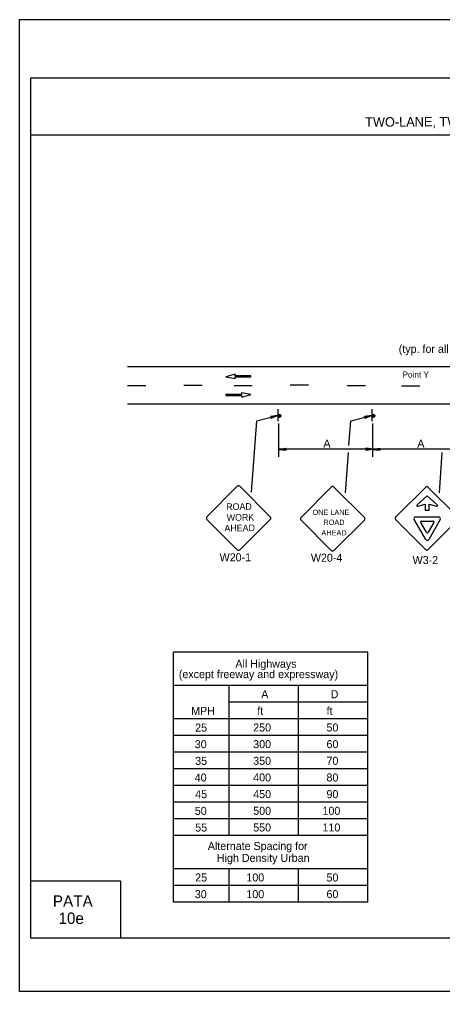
# Model space of a CAD drawing. Extents: x -14145 to -13662, y 30244 to 30661.
# Drawn here: x -13790.17 to -13779.07, y 30505.81 to 30531.31 of the extents above; entities that cross this region are included whole.
import ezdxf

# ---------------------------------------------------------------- set-up
doc = ezdxf.new("R2010")
doc.units = 0
for name, color, linetype in [('1', 7, 'Continuous'), ('10', 7, 'Continuous'), ('2', 7, 'Continuous'), ('3', 7, 'Continuous'), ('4', 7, 'Continuous'), ('61', 7, 'Continuous')]:
    doc.layers.add(name, color=color, linetype=linetype)

msp = doc.modelspace()

# ---------------------------------------------------------------- linework, layer by layer
at = {"layer": '1'}
for p, q in [((-13787.336, 30522.204), (-13761.056, 30522.204)), ((-13784.513, 30522.002), (-13784.754, 30521.935)), ((-13784.513, 30521.956), (-13784.513, 30522.002)), ((-13784.754, 30521.935), (-13784.51, 30521.889)), ((-13784.096, 30521.956), (-13784.513, 30521.956)), ((-13784.51, 30521.889), (-13784.51, 30521.934)), ((-13784.51, 30521.934), (-13784.096, 30521.934)), ((-13784.096, 30521.934), (-13784.096, 30521.956)), ((-13786.856, 30521.694), (-13787.336, 30521.694)), ((-13785.38, 30521.706), (-13785.86, 30521.706)), ((-13784.34, 30521.466), (-13784.754, 30521.466)), ((-13784.754, 30521.466), (-13784.754, 30521.444)), ((-13784.06, 30521.7), (-13784.54, 30521.7)), ((-13784.096, 30521.465), (-13784.34, 30521.511)), ((-13784.34, 30521.511), (-13784.34, 30521.466)), ((-13784.338, 30521.399), (-13784.096, 30521.465)), ((-13782.584, 30521.712), (-13783.064, 30521.712)), ((-13781.09, 30521.7), (-13781.57, 30521.7)), ((-13779.662, 30521.688), (-13780.142, 30521.688)), ((-13787.336, 30521.22), (-13761.056, 30521.22)), ((-13784.754, 30521.444), (-13784.338, 30521.444)), ((-13784.338, 30521.444), (-13784.338, 30521.399)), ((-13783.391, 30521.081), (-13783.391, 30520.769)), ((-13783.391, 30521.081), (-13783.391, 30520.769)), ((-13780.925, 30521.081), (-13780.925, 30520.769)), ((-13780.925, 30521.081), (-13780.925, 30520.769)), ((-13784.081, 30518.904), (-13783.944, 30520.774)), ((-13783.944, 30520.774), (-13783.397, 30520.914)), ((-13783.361, 30519.832), (-13783.361, 30520.706)), ((-13781.525, 30520.131), (-13781.478, 30520.774)), ((-13781.478, 30520.774), (-13780.931, 30520.914)), ((-13780.895, 30519.832), (-13780.895, 30520.706)), ((-13780.895, 30520.036), (-13783.361, 30520.036)), ((-13781.616, 30518.891), (-13781.539, 30519.945)), ((-13778.429, 30520.036), (-13780.895, 30520.036)), ((-13779.15, 30518.891), (-13779.073, 30519.945)), ((-13784.457, 30519.062), (-13785.252, 30518.259)), ((-13783.588, 30518.259), (-13784.391, 30519.062)), ((-13781.987, 30519.041), (-13782.782, 30518.238)), ((-13781.118, 30518.238), (-13781.921, 30519.041)), ((-13780.303, 30518.247), (-13779.507, 30519.041)), ((-13779.455, 30519.041), (-13778.659, 30518.247)), ((-13779.47, 30518.81), (-13779.734, 30518.571)), ((-13779.205, 30518.571), (-13779.47, 30518.81)), ((-13779.718, 30518.54), (-13779.526, 30518.59)), ((-13779.526, 30518.59), (-13779.526, 30518.431)), ((-13779.526, 30518.431), (-13779.414, 30518.431)), ((-13779.414, 30518.431), (-13779.414, 30518.59)), ((-13779.414, 30518.59), (-13779.222, 30518.54)), ((-13785.252, 30518.193), (-13784.457, 30517.398)), ((-13784.391, 30517.398), (-13783.588, 30518.193)), ((-13782.782, 30518.172), (-13781.987, 30517.377)), ((-13781.921, 30517.377), (-13781.118, 30518.172)), ((-13779.507, 30517.398), (-13780.303, 30518.193)), ((-13779.509, 30517.666), (-13779.811, 30518.189)), ((-13779.771, 30518.259), (-13779.167, 30518.259)), ((-13779.618, 30518.15), (-13779.319, 30518.15)), ((-13778.659, 30518.193), (-13779.455, 30517.398)), ((-13779.127, 30518.189), (-13779.428, 30517.666)), ((-13779.491, 30517.853), (-13779.64, 30518.111)), ((-13779.297, 30518.111), (-13779.446, 30517.853)), ((-13786.126, 30508.154), (-13786.126, 30514.71)), ((-13781.027, 30514.71), (-13786.126, 30514.71)), ((-13781.027, 30508.154), (-13781.027, 30514.71)), ((-13781.027, 30513.836), (-13786.128, 30513.836)), ((-13784.669, 30509.902), (-13784.669, 30513.836)), ((-13782.849, 30509.902), (-13782.849, 30513.836)), ((-13781.027, 30513.398), (-13784.669, 30513.398)), ((-13781.027, 30512.961), (-13786.128, 30512.961)), ((-13781.027, 30512.524), (-13786.128, 30512.524)), ((-13781.027, 30512.087), (-13786.128, 30512.087)), ((-13781.027, 30511.65), (-13786.128, 30511.65)), ((-13781.027, 30511.213), (-13786.128, 30511.213)), ((-13781.027, 30510.776), (-13786.128, 30510.776)), ((-13781.027, 30510.339), (-13786.128, 30510.339)), ((-13781.027, 30509.902), (-13786.128, 30509.902)), ((-13781.027, 30509.028), (-13786.128, 30509.028)), ((-13784.669, 30508.154), (-13784.669, 30509.028)), ((-13782.849, 30508.154), (-13782.849, 30509.028)), ((-13781.027, 30508.591), (-13786.128, 30508.591)), ((-13781.027, 30508.154), (-13786.126, 30508.154))]:
    msp.add_line(p, q, dxfattribs=at)
for points in [[(-13783.577, 30520.89), (-13783.565, 30520.878), (-13783.397, 30520.914), (-13783.577, 30520.89), (-13783.583, 30520.896), (-13783.397, 30520.914), (-13783.559, 30520.86), (-13783.565, 30520.848), (-13783.397, 30520.914), (-13783.571, 30520.836), (-13783.565, 30520.848)], [(-13781.111, 30520.89), (-13781.099, 30520.878), (-13780.931, 30520.914), (-13781.111, 30520.89), (-13781.117, 30520.896), (-13780.931, 30520.914), (-13781.093, 30520.86), (-13781.099, 30520.848), (-13780.931, 30520.914), (-13781.105, 30520.836), (-13781.099, 30520.848)], [(-13783.181, 30520.006), (-13783.187, 30520.018), (-13783.361, 30520.03), (-13783.181, 30520.006), (-13783.175, 30520), (-13783.361, 30520.03), (-13783.187, 30520.036), (-13783.181, 30520.048), (-13783.361, 30520.03), (-13783.175, 30520.06), (-13783.181, 30520.048)], [(-13781.075, 30520.06), (-13781.069, 30520.042), (-13780.895, 30520.036), (-13781.075, 30520.06), (-13781.081, 30520.066), (-13780.895, 30520.036), (-13781.069, 30520.03), (-13781.075, 30520.012), (-13780.895, 30520.036), (-13781.081, 30520.006), (-13781.075, 30520.012)], [(-13780.715, 30520.006), (-13780.721, 30520.018), (-13780.895, 30520.03), (-13780.715, 30520.006), (-13780.709, 30520), (-13780.895, 30520.03), (-13780.721, 30520.036), (-13780.715, 30520.048), (-13780.895, 30520.03), (-13780.709, 30520.06), (-13780.715, 30520.048)]]:
    msp.add_lwpolyline(points, dxfattribs=at)
for centre in [(-13783.352, 30520.908), (-13780.886, 30520.908)]:
    msp.add_circle(centre, 0.0408, dxfattribs=at)
for centre, radius, start, end in [((-13783.357, 30520.916), 0.0214, 189.521, 184.2501), ((-13780.891, 30520.916), 0.0214, 189.521, 184.2501), ((-13784.424, 30519.029), 0.0465, 45, 135), ((-13781.954, 30519.008), 0.0465, 45, 135), ((-13779.482, 30519.015), 0.0376, 45, 135), ((-13779.722, 30518.558), 0.0178, 132.5836, 284.3022), ((-13779.217, 30518.558), 0.0178, 255.6978, 47.4164), ((-13785.219, 30518.226), 0.0465, 135, 225), ((-13783.621, 30518.226), 0.0465, 315, 45), ((-13782.749, 30518.206), 0.0465, 135, 225), ((-13781.151, 30518.205), 0.0465, 315, 45), ((-13780.276, 30518.22), 0.0376, 135, 225), ((-13779.77, 30518.212), 0.0467, 90.012, 209.9768), ((-13779.617, 30518.124), 0.0259, 90.0037, 210.0207), ((-13779.319, 30518.124), 0.0259, 329.9793, 89.9963), ((-13779.167, 30518.212), 0.0467, 330.0232, 89.988), ((-13779.468, 30517.689), 0.0467, 210.0113, 329.9887), ((-13779.468, 30517.866), 0.026, 210.0215, 329.9785), ((-13784.424, 30517.431), 0.0465, 225, 315), ((-13779.481, 30517.425), 0.0376, 225, 315), ((-13781.954, 30517.41), 0.0465, 225, 315)]:
    msp.add_arc(centre, radius, start, end, dxfattribs=at)
at = {"layer": '10'}
for p, q in [((-13789.874, 30529.777), (-13758.422, 30529.777)), ((-13789.874, 30507.207), (-13789.874, 30529.777)), ((-13789.874, 30528.277), (-13758.422, 30528.277)), ((-13789.874, 30508.707), (-13787.524, 30508.707)), ((-13787.524, 30508.707), (-13787.524, 30507.207)), ((-13758.422, 30507.207), (-13789.874, 30507.207))]:
    msp.add_line(p, q, dxfattribs=at)
at = {"layer": '61'}
msp.add_lwpolyline([(-13790.174, 30531.307), (-13757.174, 30531.307), (-13757.174, 30505.807), (-13790.174, 30505.807)], close=True, dxfattribs=at)

# ---------------------------------------------------------------- texts
at = {"layer": '1'}
for s, height, rotation, p in [('ROAD', 0.1735, 0.7566, (-13784.744, 30518.438)), ('WORK', 0.1733, 0.7588, (-13784.731, 30518.153)), ('AHEAD', 0.1735, 0.7481, (-13784.791, 30517.875))]:
    msp.add_text(s, height=height, rotation=rotation, dxfattribs=at).set_placement(p)
for s, height, p in [('ONE LANE', 0.1386, (-13782.479, 30518.31)), ('ROAD', 0.1389, (-13782.194, 30518.047)), ('AHEAD', 0.139, (-13782.246, 30517.77))]:
    msp.add_text(s, height=height, dxfattribs=at).set_placement(p)
at = {"layer": '2'}
for s, p in [('(typ. for all tapers)', (-13780.217, 30522.561)), ('A', (-13782.195, 30520.076)), ('A', (-13779.729, 30520.076)), ('W20-1', (-13784.919, 30517.092)), ('W20-4', (-13782.523, 30517.081)), ('W3-2', (-13779.853, 30517.021)), ('A', (-13783.825, 30513.502)), ('D', (-13782.004, 30513.502)), ('MPH', (-13785.665, 30513.064)), ('ft', (-13783.93, 30513.064)), ('ft', (-13782.111, 30513.064)), ('25', (-13785.56, 30512.627)), ('250', (-13784.037, 30512.629)), ('50', (-13782.113, 30512.629)), ('30', (-13785.571, 30512.19)), ('300', (-13784.037, 30512.192)), ('60', (-13782.113, 30512.192)), ('35', (-13785.56, 30511.753)), ('350', (-13784.037, 30511.755)), ('70', (-13782.113, 30511.755)), ('40', (-13785.571, 30511.316)), ('400', (-13784.037, 30511.318)), ('80', (-13782.113, 30511.318)), ('45', (-13785.56, 30510.879)), ('450', (-13784.037, 30510.88)), ('90', (-13782.113, 30510.88)), ('50', (-13785.57, 30510.442)), ('500', (-13784.037, 30510.443)), ('100', (-13782.218, 30510.443)), ('55', (-13785.56, 30510.005)), ('550', (-13784.037, 30510.006)), ('110', (-13782.218, 30510.006)), ('25', (-13785.56, 30508.694)), ('100', (-13784.216, 30508.694)), ('50', (-13782.113, 30508.694)), ('30', (-13785.57, 30508.257)), ('100', (-13784.216, 30508.257)), ('60', (-13782.113, 30508.257))]:
    msp.add_text(s, height=0.21, dxfattribs=at).set_placement(p)
at = {"layer": '3'}
for s, height, p in [('Point Y', 0.16, (-13780.116, 30521.912)), ('All Highways', 0.20979, (-13784.505, 30514.301)), ('(except freeway and expressway)', 0.21, (-13785.99, 30514.028)), ('Alternate Spacing for', 0.20979, (-13785.228, 30509.521)), ('High Density Urban', 0.20979, (-13784.99, 30509.207))]:
    msp.add_text(s, height=height, dxfattribs=at).set_placement(p)
at = {"layer": '4'}
msp.add_text('TWO-LANE, TWO-WAY ROADWAY - SELF-REGULATING LANE CLOSURE', height=0.25, rotation=0.31, dxfattribs=at).set_placement((-13781.097, 30528.49))
for s, p in [('PATA', (-13789.296, 30508.03)), ('10e', (-13789.15, 30507.58))]:
    msp.add_text(s, height=0.3, dxfattribs=at).set_placement(p)

doc.saveas('drawing.dxf')
